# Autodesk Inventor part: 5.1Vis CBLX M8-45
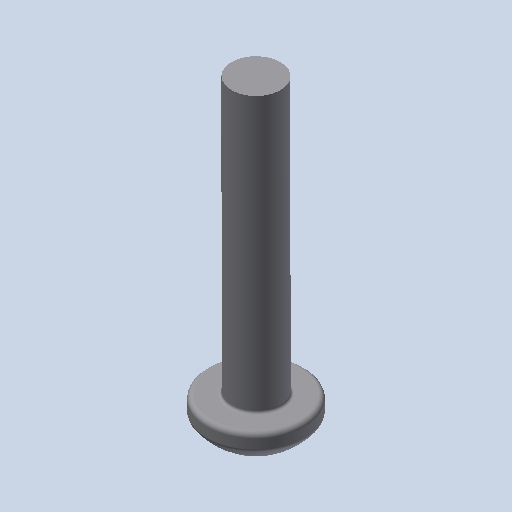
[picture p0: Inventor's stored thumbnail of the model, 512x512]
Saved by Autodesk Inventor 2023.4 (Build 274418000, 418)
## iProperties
Created: 2011-01
Part Number: 5.1Vis CBLX M8-45
Document SubType Name: Modeling
Designer: eric
Density: 1 g/cm^3
Mass: 3.13907 g
Surface Area: 17.5326 cm^2
Volume: 3.13907 cm^3
Material: Générique
Appearance: Par défaut
Author: eric
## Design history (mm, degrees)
feature "Base1"
node "Corps solides"
node "Corps surfaciques"
node "Solide1"
